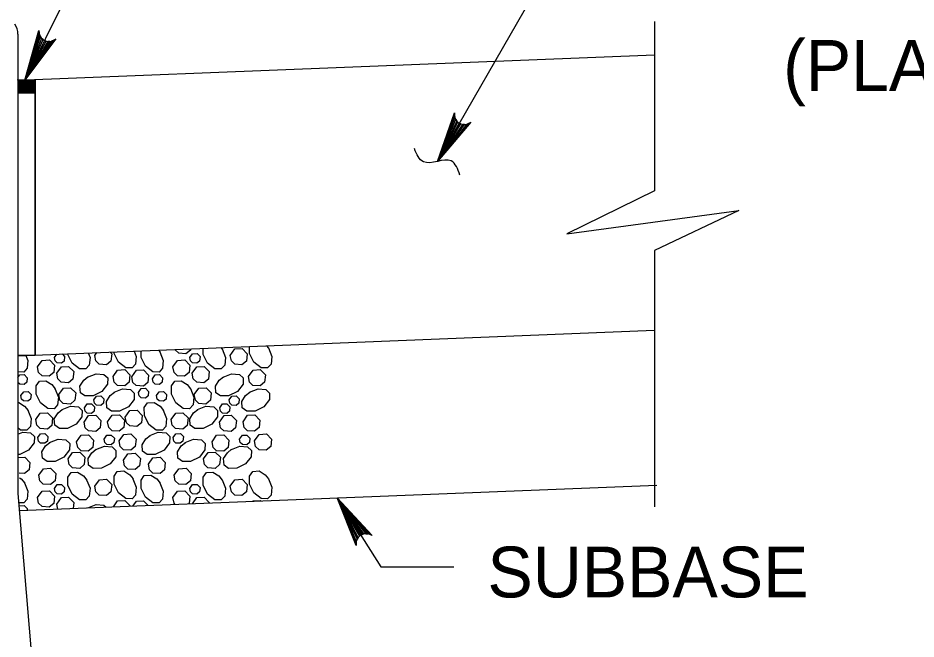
# Model space of a CAD drawing. Extents: x 2084213 to 2099800, y 976677 to 981262.
# Drawn here: x 2094550.7 to 2094724.7, y 976998 to 977118.3 of the extents above; entities that cross this region are included whole.
import ezdxf

# ---------------------------------------------------------------- set-up
doc = ezdxf.new("R2010")
doc.units = 0
doc.layers.add('1', color=7, linetype='Continuous')

msp = doc.modelspace()

# ---------------------------------------------------------------- linework, layer by layer
at = {"layer": '1'}
for p, q in [((2094594.99, 977193.27), (2094552.07, 977106.28)), ((2094631.96, 977090.51), (2094665.97, 977149.63)), ((2094674.05, 977117.63), (2094674.05, 977084.81)), ((2094550.71, 977115.18), (2094550.71, 977026.18)), ((2094550.71, 977106.22), (2094674.05, 977111.16)), ((2094550.71, 977106.2), (2094554.05, 977106.2)), ((2094550.71, 977106.05), (2094554.05, 977106.05)), ((2094550.71, 977105.9), (2094554.05, 977105.9)), ((2094550.71, 977105.75), (2094554.05, 977105.75)), ((2094554.05, 977106.36), (2094554.05, 977053)), ((2094550.71, 977105.6), (2094554.05, 977105.6)), ((2094550.71, 977105.45), (2094554.05, 977105.45)), ((2094550.71, 977105.3), (2094554.05, 977105.3)), ((2094550.71, 977105.15), (2094554.05, 977105.15)), ((2094550.71, 977105), (2094554.05, 977105)), ((2094550.71, 977104.85), (2094554.05, 977104.85)), ((2094550.71, 977104.7), (2094554.05, 977104.7)), ((2094550.71, 977104.55), (2094554.05, 977104.55)), ((2094550.71, 977104.4), (2094554.05, 977104.4)), ((2094550.71, 977104.25), (2094554.05, 977104.25)), ((2094550.71, 977104.1), (2094554.05, 977104.1)), ((2094550.71, 977103.95), (2094554.05, 977103.95)), ((2094550.71, 977103.8), (2094554.05, 977103.8)), ((2094674.05, 977073.27), (2094674.05, 977023.6)), ((2094550.71, 977052.86), (2094674.05, 977057.8)), ((2094550.99, 977022.85), (2094674.45, 977027.79)), ((2094550.71, 977026.18), (2094559.62, 976919.33)), ((2094612.54, 977025.31), (2094621, 977011.95)), ((2094621, 977011.95), (2094635.14, 977011.95))]:
    msp.add_line(p, q, dxfattribs=at)
for points in [[(2094552.07, 977106.28), (2094554.75, 977115.87), (2094554.82, 977115.41), (2094554.89, 977114.96), (2094555.1, 977114.64), (2094555.3, 977114.32), (2094555.57, 977114.12), (2094555.84, 977113.93), (2094556.16, 977113.83), (2094556.48, 977113.74), (2094556.86, 977113.77), (2094557.24, 977113.8), (2094557.64, 977114.02), (2094558.04, 977114.24), (2094552.07, 977106.28), (2094557.64, 977114.02), (2094557.24, 977113.8), (2094552.07, 977106.28), (2094556.86, 977113.77), (2094556.48, 977113.74), (2094552.07, 977106.28), (2094556.16, 977113.83), (2094555.84, 977113.93), (2094552.07, 977106.28), (2094555.57, 977114.12), (2094555.3, 977114.32), (2094552.07, 977106.28), (2094555.1, 977114.64), (2094554.89, 977114.96), (2094552.07, 977106.28), (2094554.82, 977115.41)], [(2094631.96, 977090.51), (2094635.25, 977099.91), (2094635.28, 977099.45), (2094635.32, 977098.99), (2094635.51, 977098.66), (2094635.7, 977098.33), (2094635.95, 977098.11), (2094636.21, 977097.9), (2094636.52, 977097.79), (2094636.84, 977097.67), (2094637.22, 977097.68), (2094637.6, 977097.68), (2094638.01, 977097.88), (2094638.43, 977098.08), (2094631.96, 977090.51), (2094638.01, 977097.88), (2094637.6, 977097.68), (2094631.96, 977090.51), (2094637.22, 977097.68), (2094636.84, 977097.67), (2094631.96, 977090.51), (2094636.52, 977097.79), (2094636.21, 977097.9), (2094631.96, 977090.51), (2094635.95, 977098.11), (2094635.7, 977098.33), (2094631.96, 977090.51), (2094635.51, 977098.66), (2094635.32, 977098.99), (2094631.96, 977090.51), (2094635.28, 977099.45)], [(2094674.05, 977084.81), (2094657.03, 977076.49), (2094690.33, 977081.01), (2094674.05, 977073.27)], [(2094568.56, 977053.58), (2094568.87, 977053.25), (2094568.73, 977051.82), (2094567.86, 977051.1), (2094566.47, 977051.2), (2094565.82, 977051.84), (2094565.6, 977052.93)], [(2094573.23, 977053.76), (2094573.64, 977052.74), (2094573.51, 977051.22), (2094572.82, 977050.5), (2094571.59, 977050.52), (2094570.2, 977051.62), (2094569.35, 977053.31), (2094569.35, 977053.61)], [(2094578.22, 977053.59), (2094578.87, 977051.94), (2094578.74, 977050.42), (2094578.05, 977049.7), (2094576.82, 977049.72), (2094575.43, 977050.82), (2094574.58, 977052.51), (2094574.56, 977053.82)], [(2094577.92, 977053.95), (2094578.26, 977053.52)], [(2094584.14, 977054.2), (2094584.12, 977053.96), (2094583.25, 977053.24), (2094581.86, 977053.34), (2094581.2, 977053.97), (2094581.18, 977054.08)], [(2094590.25, 977054.18), (2094590.91, 977052.53), (2094590.77, 977051.01), (2094590.09, 977050.29), (2094588.86, 977050.31), (2094587.46, 977051.4), (2094586.62, 977053.09), (2094586.59, 977054.3)], [(2094590.03, 977054.43), (2094590.29, 977054.11)], [(2094591.84, 977052.93), (2094592.72, 977054.18), (2094594.13, 977054.26), (2094595.11, 977053.25), (2094594.96, 977051.82), (2094594.09, 977051.1), (2094592.7, 977051.2), (2094592.05, 977051.84), (2094591.84, 977052.93)], [(2094599.22, 977054.39), (2094599.87, 977052.74), (2094599.74, 977051.22), (2094599.06, 977050.5), (2094597.83, 977050.52), (2094596.43, 977051.62), (2094595.58, 977053.31), (2094595.56, 977054.66)], [(2094598.89, 977054.79), (2094599.26, 977054.32)], [(2094552.25, 977052.92), (2094552.64, 977051.94), (2094552.51, 977050.42), (2094551.82, 977049.7), (2094550.71, 977049.72)], [(2094554.51, 977050.7), (2094555.39, 977051.96), (2094556.8, 977052.04), (2094557.78, 977051.02), (2094557.64, 977049.6), (2094556.77, 977048.88), (2094555.38, 977048.98), (2094554.72, 977049.61), (2094554.51, 977050.7)], [(2094559.25, 977053.2), (2094559.75, 977052.68), (2094559.67, 977051.83), (2094559.14, 977051.39), (2094558.31, 977051.46), (2094557.92, 977051.84), (2094557.79, 977052.49)], [(2094557.79, 977052.49), (2094558.26, 977053.16)], [(2094564.32, 977053.41), (2094564.67, 977052.53), (2094564.54, 977051.01), (2094563.86, 977050.29), (2094562.63, 977050.31), (2094561.23, 977051.4), (2094560.38, 977053.09), (2094560.38, 977053.25)], [(2094565.6, 977052.93), (2094565.99, 977053.47)], [(2094580.74, 977050.7), (2094581.62, 977051.96), (2094583.03, 977052.04), (2094584.01, 977051.02), (2094583.87, 977049.6), (2094583, 977048.88), (2094581.61, 977048.98), (2094580.95, 977049.61), (2094580.74, 977050.7)], [(2094584.02, 977052.49), (2094584.55, 977053.24), (2094585.4, 977053.29), (2094585.98, 977052.68), (2094585.9, 977051.83), (2094585.38, 977051.39), (2094584.54, 977051.46), (2094584.15, 977051.84), (2094584.02, 977052.49)], [(2094558.24, 977049.46), (2094559.12, 977050.71), (2094560.53, 977050.79), (2094561.51, 977049.78), (2094561.37, 977048.35), (2094560.5, 977047.63), (2094559.11, 977047.73), (2094558.45, 977048.37), (2094558.24, 977049.46)], [(2094569.13, 977048.84), (2094570.02, 977050.09), (2094571.43, 977050.17), (2094572.4, 977049.16), (2094572.26, 977047.73), (2094571.39, 977047.01), (2094570, 977047.11), (2094569.35, 977047.74), (2094569.14, 977048.83)], [(2094572.76, 977048.78), (2094573.65, 977050.04), (2094575.05, 977050.12), (2094576.03, 977049.1), (2094575.89, 977047.68), (2094575.02, 977046.96), (2094573.63, 977047.06), (2094572.98, 977047.69), (2094572.76, 977048.78)], [(2094584.47, 977049.46), (2094585.35, 977050.71), (2094586.76, 977050.79), (2094587.74, 977049.78), (2094587.6, 977048.35), (2094586.73, 977047.63), (2094585.34, 977047.73), (2094584.68, 977048.37), (2094584.47, 977049.46)], [(2094595.37, 977048.84), (2094596.25, 977050.09), (2094597.66, 977050.17), (2094598.64, 977049.16), (2094598.49, 977047.73), (2094597.62, 977047.01), (2094596.23, 977047.11), (2094595.58, 977047.74), (2094595.37, 977048.83)], [(2094550.71, 977048.63), (2094551.08, 977049.15), (2094551.92, 977049.2), (2094552.51, 977048.59), (2094552.42, 977047.73), (2094551.9, 977047.3), (2094551.07, 977047.36), (2094550.71, 977047.7)], [(2094564.21, 977048.72), (2094565.86, 977049.37), (2094567.38, 977049.24), (2094568.1, 977048.56), (2094568.08, 977047.33), (2094566.98, 977045.93), (2094565.29, 977045.09), (2094563.7, 977045.06), (2094562.8, 977045.69), (2094562.72, 977046.96), (2094563.45, 977048.1), (2094564.28, 977048.76)], [(2094576.78, 977048.39), (2094577.31, 977049.15), (2094578.15, 977049.2), (2094578.74, 977048.59), (2094578.66, 977047.73), (2094578.13, 977047.3), (2094577.3, 977047.36), (2094576.91, 977047.74), (2094576.78, 977048.39)], [(2094590.45, 977048.72), (2094592.1, 977049.37), (2094593.61, 977049.24), (2094594.33, 977048.56), (2094594.31, 977047.33), (2094593.22, 977045.93), (2094591.53, 977045.09), (2094589.93, 977045.06), (2094589.04, 977045.69), (2094588.95, 977046.96), (2094589.68, 977048.1), (2094590.51, 977048.76)], [(2094557.88, 977046.49), (2094558.54, 977044.84), (2094558.4, 977043.32), (2094557.72, 977042.6), (2094556.49, 977042.63), (2094555.09, 977043.72), (2094554.25, 977045.41), (2094554.22, 977047), (2094554.86, 977047.9), (2094556.12, 977047.98), (2094557.26, 977047.26), (2094557.92, 977046.42)], [(2094558.63, 977045.33), (2094559.51, 977046.58), (2094560.92, 977046.66), (2094561.9, 977045.65), (2094561.76, 977044.23), (2094560.89, 977043.5), (2094559.5, 977043.6), (2094558.84, 977044.24), (2094558.63, 977045.33)], [(2094574.05, 977045.75), (2094574.58, 977046.5), (2094575.42, 977046.55), (2094576.01, 977045.94), (2094575.92, 977045.08), (2094575.4, 977044.65), (2094574.57, 977044.71), (2094574.18, 977045.09), (2094574.05, 977045.75)], [(2094584.11, 977046.49), (2094584.77, 977044.84), (2094584.64, 977043.32), (2094583.95, 977042.6), (2094582.72, 977042.63), (2094581.32, 977043.72), (2094580.48, 977045.41), (2094580.45, 977047), (2094581.09, 977047.9), (2094582.36, 977047.98), (2094583.49, 977047.26), (2094584.16, 977046.42)], [(2094584.86, 977045.33), (2094585.74, 977046.58), (2094587.15, 977046.66), (2094588.13, 977045.65), (2094587.99, 977044.23), (2094587.12, 977043.5), (2094585.73, 977043.6), (2094585.08, 977044.24), (2094584.86, 977045.33)], [(2094551.29, 977045.13), (2094551.82, 977045.88), (2094552.67, 977045.93), (2094553.25, 977045.32), (2094553.17, 977044.46), (2094552.65, 977044.03), (2094551.81, 977044.09), (2094551.42, 977044.47), (2094551.29, 977045.13)], [(2094565.4, 977044.3), (2094565.93, 977045.05), (2094566.78, 977045.1), (2094567.36, 977044.49), (2094567.28, 977043.64), (2094566.76, 977043.2), (2094565.92, 977043.26), (2094565.53, 977043.64), (2094565.4, 977044.3)], [(2094569.33, 977045.77), (2094570.98, 977046.43), (2094572.5, 977046.3), (2094573.22, 977045.61), (2094573.2, 977044.38), (2094572.1, 977042.98), (2094570.41, 977042.14), (2094568.82, 977042.11), (2094567.92, 977042.75), (2094567.84, 977044.02), (2094568.57, 977045.15), (2094569.4, 977045.81)], [(2094577.52, 977045.13), (2094578.05, 977045.88), (2094578.9, 977045.93), (2094579.49, 977045.32), (2094579.4, 977044.46), (2094578.88, 977044.03), (2094578.04, 977044.09), (2094577.65, 977044.47), (2094577.52, 977045.13)], [(2094591.63, 977044.3), (2094592.16, 977045.05), (2094593.01, 977045.1), (2094593.59, 977044.49), (2094593.51, 977043.64), (2094592.99, 977043.2), (2094592.15, 977043.26), (2094591.76, 977043.64), (2094591.63, 977044.3)], [(2094595.57, 977045.77), (2094597.22, 977046.43), (2094598.73, 977046.3), (2094599.45, 977045.61), (2094599.43, 977044.38), (2094598.34, 977042.98), (2094596.65, 977042.14), (2094595.05, 977042.11), (2094594.16, 977042.75), (2094594.07, 977044.02), (2094594.8, 977045.15), (2094595.63, 977045.81)], [(2094550.71, 977043.81), (2094550.87, 977043.82), (2094552, 977043.09), (2094552.67, 977042.26)], [(2094559.25, 977042.41), (2094560.9, 977043.06), (2094562.41, 977042.93), (2094563.13, 977042.25), (2094563.11, 977041.02), (2094562.02, 977039.62), (2094560.33, 977038.78), (2094558.74, 977038.75), (2094557.84, 977039.38), (2094557.75, 977040.65), (2094558.48, 977041.79), (2094559.31, 977042.45)], [(2094563.58, 977042.77), (2094564.11, 977043.52), (2094564.96, 977043.57), (2094565.54, 977042.96), (2094565.46, 977042.11), (2094564.94, 977041.67), (2094564.1, 977041.73), (2094563.71, 977042.11), (2094563.58, 977042.77)], [(2094578.86, 977042.33), (2094579.51, 977040.68), (2094579.38, 977039.16), (2094578.69, 977038.44), (2094577.46, 977038.46), (2094576.07, 977039.56), (2094575.22, 977041.25), (2094575.19, 977042.84), (2094575.83, 977043.74), (2094577.1, 977043.82), (2094578.23, 977043.09), (2094578.9, 977042.26)], [(2094585.48, 977042.41), (2094587.13, 977043.06), (2094588.65, 977042.93), (2094589.37, 977042.25), (2094589.34, 977041.02), (2094588.25, 977039.62), (2094586.56, 977038.78), (2094584.97, 977038.75), (2094584.07, 977039.38), (2094583.99, 977040.65), (2094584.71, 977041.79), (2094585.55, 977042.45)], [(2094589.81, 977042.77), (2094590.34, 977043.52), (2094591.19, 977043.57), (2094591.77, 977042.96), (2094591.69, 977042.11), (2094591.17, 977041.67), (2094590.33, 977041.73), (2094589.94, 977042.11), (2094589.81, 977042.77)], [(2094552.62, 977042.33), (2094553.28, 977040.68), (2094553.15, 977039.16), (2094552.46, 977038.44), (2094551.23, 977038.46), (2094550.71, 977038.87)], [(2094554.16, 977040.48), (2094555.04, 977041.73), (2094556.45, 977041.81), (2094557.43, 977040.8), (2094557.29, 977039.37), (2094556.42, 977038.65), (2094555.03, 977038.75), (2094554.37, 977039.38), (2094554.16, 977040.48)], [(2094563.52, 977040.01), (2094564.4, 977041.26), (2094565.81, 977041.35), (2094566.79, 977040.33), (2094566.65, 977038.91), (2094565.78, 977038.18), (2094564.39, 977038.28), (2094563.74, 977038.92), (2094563.52, 977040.01)], [(2094568.07, 977040.06), (2094568.96, 977041.32), (2094570.37, 977041.4), (2094571.34, 977040.38), (2094571.2, 977038.96), (2094570.33, 977038.24), (2094568.94, 977038.34), (2094568.29, 977038.97), (2094568.08, 977040.06)], [(2094571.5, 977040.98), (2094572.38, 977042.24), (2094573.79, 977042.32), (2094574.77, 977041.3), (2094574.62, 977039.88), (2094573.75, 977039.16), (2094572.36, 977039.26), (2094571.71, 977039.89), (2094571.5, 977040.98)], [(2094580.39, 977040.48), (2094581.27, 977041.73), (2094582.68, 977041.81), (2094583.66, 977040.8), (2094583.52, 977039.37), (2094582.65, 977038.65), (2094581.26, 977038.75), (2094580.6, 977039.38), (2094580.39, 977040.48)], [(2094589.75, 977040.01), (2094590.64, 977041.26), (2094592.04, 977041.35), (2094593.02, 977040.33), (2094592.88, 977038.91), (2094592.01, 977038.18), (2094590.62, 977038.28), (2094589.97, 977038.92), (2094589.75, 977040.01)], [(2094594.31, 977040.06), (2094595.19, 977041.32), (2094596.6, 977041.4), (2094597.58, 977040.38), (2094597.43, 977038.96), (2094596.56, 977038.24), (2094595.17, 977038.34), (2094594.52, 977038.97), (2094594.31, 977040.06)], [(2094550.71, 977037.66), (2094551.66, 977038.03), (2094553.17, 977037.9), (2094553.9, 977037.22), (2094553.87, 977035.99), (2094552.78, 977034.59), (2094551.09, 977033.74), (2094550.71, 977033.74)], [(2094576.24, 977037.38), (2094577.89, 977038.03), (2094579.41, 977037.9), (2094580.13, 977037.22), (2094580.1, 977035.99), (2094579.01, 977034.59), (2094577.32, 977033.74), (2094575.73, 977033.71), (2094574.83, 977034.35), (2094574.75, 977035.62), (2094575.47, 977036.76), (2094576.31, 977037.42)], [(2094554.56, 977036.99), (2094555.09, 977037.74), (2094555.94, 977037.79), (2094556.52, 977037.18), (2094556.44, 977036.33), (2094555.92, 977035.89), (2094555.08, 977035.95), (2094554.69, 977036.33), (2094554.56, 977036.99)], [(2094556.85, 977036.02), (2094558.5, 977036.68), (2094560.01, 977036.55), (2094560.74, 977035.86), (2094560.71, 977034.63), (2094559.62, 977033.23), (2094557.93, 977032.39), (2094556.34, 977032.36), (2094555.44, 977033), (2094555.35, 977034.27), (2094556.08, 977035.4), (2094556.91, 977036.07)], [(2094562.08, 977036.18), (2094562.96, 977037.44), (2094564.37, 977037.52), (2094565.35, 977036.5), (2094565.2, 977035.08), (2094564.33, 977034.36), (2094562.94, 977034.46), (2094562.29, 977035.09), (2094562.08, 977036.18)], [(2094567.43, 977036.7), (2094567.96, 977037.45), (2094568.8, 977037.5), (2094569.39, 977036.89), (2094569.31, 977036.04), (2094568.78, 977035.6), (2094567.95, 977035.66), (2094567.56, 977036.04), (2094567.43, 977036.7)], [(2094570.32, 977036.37), (2094571.2, 977037.63), (2094572.61, 977037.71), (2094573.59, 977036.69), (2094573.45, 977035.27), (2094572.58, 977034.55), (2094571.19, 977034.65), (2094570.53, 977035.28), (2094570.32, 977036.37)], [(2094580.79, 977036.99), (2094581.32, 977037.74), (2094582.17, 977037.79), (2094582.76, 977037.18), (2094582.67, 977036.33), (2094582.15, 977035.89), (2094581.31, 977035.95), (2094580.92, 977036.33), (2094580.79, 977036.99)], [(2094583.08, 977036.02), (2094584.73, 977036.68), (2094586.25, 977036.55), (2094586.97, 977035.86), (2094586.94, 977034.63), (2094585.85, 977033.23), (2094584.16, 977032.39), (2094582.57, 977032.36), (2094581.67, 977033), (2094581.59, 977034.27), (2094582.31, 977035.4), (2094583.15, 977036.07)], [(2094588.31, 977036.18), (2094589.19, 977037.44), (2094590.6, 977037.52), (2094591.58, 977036.5), (2094591.44, 977035.08), (2094590.57, 977034.36), (2094589.17, 977034.46), (2094588.52, 977035.09), (2094588.31, 977036.18)], [(2094593.66, 977036.7), (2094594.19, 977037.45), (2094595.03, 977037.5), (2094595.62, 977036.89), (2094595.54, 977036.04), (2094595.02, 977035.6), (2094594.18, 977035.66), (2094593.79, 977036.04), (2094593.66, 977036.7)], [(2094596.55, 977036.37), (2094597.43, 977037.63), (2094598.84, 977037.71), (2094599.82, 977036.69), (2094599.68, 977035.27), (2094598.81, 977034.55), (2094597.42, 977034.65), (2094596.76, 977035.28), (2094596.55, 977036.37)], [(2094565.81, 977034.69), (2094567.46, 977035.34), (2094568.98, 977035.21), (2094569.7, 977034.53), (2094569.68, 977033.3), (2094568.58, 977031.9), (2094566.89, 977031.05), (2094565.3, 977031.03), (2094564.41, 977031.66), (2094564.32, 977032.93), (2094565.05, 977034.07), (2094565.88, 977034.73)], [(2094592.05, 977034.69), (2094593.7, 977035.34), (2094595.21, 977035.21), (2094595.93, 977034.53), (2094595.91, 977033.3), (2094594.82, 977031.9), (2094593.13, 977031.05), (2094591.53, 977031.03), (2094590.64, 977031.66), (2094590.55, 977032.93), (2094591.28, 977034.07), (2094592.11, 977034.73)], [(2094550.71, 977033.11), (2094552.03, 977033.18), (2094553.01, 977032.17), (2094552.87, 977030.75), (2094552, 977030.02), (2094550.95, 977030.1)], [(2094560.41, 977032.86), (2094561.3, 977034.12), (2094562.71, 977034.2), (2094563.69, 977033.18), (2094563.54, 977031.76), (2094562.67, 977031.04), (2094561.28, 977031.14), (2094560.63, 977031.77), (2094560.42, 977032.86)], [(2094571.15, 977032.62), (2094572.03, 977033.87), (2094573.44, 977033.95), (2094574.42, 977032.94), (2094574.28, 977031.51), (2094573.41, 977030.79), (2094572.02, 977030.89), (2094571.36, 977031.53), (2094571.15, 977032.62)], [(2094575.97, 977031.85), (2094576.86, 977033.1), (2094578.26, 977033.18), (2094579.24, 977032.17), (2094579.1, 977030.75), (2094578.23, 977030.02), (2094576.84, 977030.12), (2094576.19, 977030.76), (2094575.97, 977031.85)], [(2094586.65, 977032.86), (2094587.53, 977034.12), (2094588.94, 977034.2), (2094589.92, 977033.18), (2094589.78, 977031.76), (2094588.91, 977031.04), (2094587.51, 977031.14), (2094586.86, 977031.77), (2094586.65, 977032.86)], [(2094554.76, 977029.71), (2094555.64, 977030.97), (2094557.05, 977031.05), (2094558.03, 977030.03), (2094557.89, 977028.61), (2094557.02, 977027.89), (2094555.62, 977027.99), (2094554.97, 977028.62), (2094554.76, 977029.71)], [(2094580.99, 977029.71), (2094581.87, 977030.97), (2094583.28, 977031.05), (2094584.26, 977030.03), (2094584.12, 977028.61), (2094583.25, 977027.89), (2094581.86, 977027.99), (2094581.2, 977028.62), (2094580.99, 977029.71)], [(2094551.02, 977029.23), (2094551.36, 977029.01), (2094552.03, 977028.17)], [(2094564.02, 977028.83), (2094564.67, 977027.18), (2094564.54, 977025.66), (2094563.86, 977024.94), (2094562.63, 977024.96), (2094561.23, 977026.06), (2094560.38, 977027.75), (2094560.36, 977029.34), (2094560.99, 977030.24), (2094562.26, 977030.32), (2094563.4, 977029.59), (2094564.06, 977028.76)], [(2094572.99, 977029.04), (2094573.64, 977027.39), (2094573.51, 977025.87), (2094572.82, 977025.15), (2094571.59, 977025.18), (2094570.2, 977026.27), (2094569.35, 977027.96), (2094569.32, 977029.55), (2094569.96, 977030.45), (2094571.23, 977030.54), (2094572.36, 977029.81), (2094573.03, 977028.98)], [(2094578.22, 977028.24), (2094578.87, 977026.59), (2094578.74, 977025.07), (2094578.05, 977024.35), (2094576.82, 977024.38), (2094575.43, 977025.47), (2094574.58, 977027.16), (2094574.55, 977028.75), (2094575.19, 977029.65), (2094576.46, 977029.74), (2094577.59, 977029.01), (2094578.26, 977028.17)], [(2094590.25, 977028.83), (2094590.91, 977027.18), (2094590.77, 977025.66), (2094590.09, 977024.94), (2094588.86, 977024.96), (2094587.46, 977026.06), (2094586.62, 977027.75), (2094586.59, 977029.34), (2094587.22, 977030.24), (2094588.49, 977030.32), (2094589.63, 977029.59), (2094590.29, 977028.76)], [(2094599.22, 977029.04), (2094599.87, 977027.39), (2094599.74, 977025.87), (2094599.06, 977025.15), (2094597.83, 977025.18), (2094596.43, 977026.27), (2094595.58, 977027.96), (2094595.55, 977029.55), (2094596.19, 977030.45), (2094597.46, 977030.54), (2094598.59, 977029.81), (2094599.26, 977028.98)], [(2094551.98, 977028.24), (2094552.64, 977026.59), (2094552.51, 977025.07), (2094551.82, 977024.35), (2094550.87, 977024.37)], [(2094557.79, 977027.14), (2094558.32, 977027.9), (2094559.16, 977027.94), (2094559.75, 977027.33), (2094559.67, 977026.48), (2094559.14, 977026.05), (2094558.31, 977026.11), (2094557.92, 977026.49), (2094557.79, 977027.14)], [(2094565.6, 977027.58), (2094566.49, 977028.83), (2094567.89, 977028.92), (2094568.87, 977027.9), (2094568.73, 977026.48), (2094567.86, 977025.75), (2094566.47, 977025.85), (2094565.82, 977026.49), (2094565.6, 977027.58)], [(2094584.02, 977027.14), (2094584.55, 977027.9), (2094585.4, 977027.94), (2094585.98, 977027.33), (2094585.9, 977026.48), (2094585.38, 977026.05), (2094584.54, 977026.11), (2094584.15, 977026.49), (2094584.02, 977027.14)], [(2094591.84, 977027.58), (2094592.72, 977028.83), (2094594.13, 977028.92), (2094595.11, 977027.9), (2094594.96, 977026.48), (2094594.09, 977025.75), (2094592.7, 977025.85), (2094592.05, 977026.49), (2094591.84, 977027.58)], [(2094554.51, 977025.36), (2094555.39, 977026.61), (2094556.8, 977026.69), (2094557.78, 977025.68), (2094557.64, 977024.25), (2094556.77, 977023.53), (2094555.38, 977023.63), (2094554.72, 977024.27), (2094554.51, 977025.36)], [(2094580.74, 977025.36), (2094581.62, 977026.61), (2094583.03, 977026.69), (2094584.01, 977025.68), (2094583.87, 977024.25), (2094583.76, 977024.16)], [(2094558.24, 977024.11), (2094559.12, 977025.37), (2094560.53, 977025.45), (2094561.51, 977024.43), (2094561.39, 977023.26)], [(2094558.43, 977023.15), (2094558.24, 977024.11)], [(2094564.23, 977023.38), (2094565.86, 977024.03), (2094567.38, 977023.9), (2094567.78, 977023.52)], [(2094569.2, 977023.58), (2094570.02, 977024.74), (2094571.43, 977024.82), (2094572.4, 977023.81), (2094572.39, 977023.71)], [(2094572.97, 977023.73), (2094573.65, 977024.69), (2094575.05, 977024.77), (2094575.95, 977023.85)], [(2094581.17, 977024.06), (2094580.95, 977024.27), (2094580.74, 977025.36)], [(2094584.53, 977024.19), (2094585.35, 977025.37), (2094586.76, 977025.45), (2094587.74, 977024.43), (2094587.73, 977024.32)], [(2094596.19, 977024.66), (2094596.25, 977024.74), (2094597.66, 977024.82), (2094597.76, 977024.72)], [(2094612.54, 977025.31), (2094619.32, 977018.02), (2094618.9, 977018.2), (2094618.48, 977018.38), (2094618.1, 977018.37), (2094617.72, 977018.36), (2094617.41, 977018.23), (2094617.1, 977018.1), (2094616.85, 977017.88), (2094616.61, 977017.66), (2094616.43, 977017.32), (2094616.26, 977016.98), (2094616.24, 977016.52), (2094616.22, 977016.06), (2094612.54, 977025.31), (2094616.24, 977016.52), (2094616.26, 977016.98), (2094612.54, 977025.31), (2094616.43, 977017.32), (2094616.61, 977017.66), (2094612.54, 977025.31), (2094616.85, 977017.88), (2094617.1, 977018.1), (2094612.54, 977025.31), (2094617.41, 977018.23), (2094617.72, 977018.36), (2094612.54, 977025.31), (2094618.1, 977018.37), (2094618.48, 977018.38), (2094612.54, 977025.31), (2094618.9, 977018.2)], [(2094550.91, 977023.79), (2094551.92, 977023.85), (2094552.51, 977023.24), (2094552.48, 977022.91)], [(2094564.23, 977023.38), (2094564.28, 977023.42)]]:
    msp.add_lwpolyline(points, dxfattribs=at)
msp.add_lwpolyline([(2094554.05, 977106.22), (2094550.71, 977106.22), (2094550.71, 977106.36), (2094550.71, 977053), (2094554.05, 977053)], close=True, dxfattribs=at)
msp.add_arc((2094547.38, 977115.18), 3.33, 0, 34.8593, dxfattribs=at)
msp.add_arc((2094547.38, 977115.18), 3.33, 0, 34.8593, dxfattribs=at)
msp.add_spline([(2094636.34, 977087.86), (2094634.64, 977090.59), (2094629.25, 977090.42), (2094627.5, 977092.99)], degree=3, dxfattribs=at)

# ---------------------------------------------------------------- texts
for s, height, p in [('(PLACED CURB TO CURB)', 9.8425, (2094698.95, 977104.17)), ('SUBBASE', 9.843, (2094641.66, 977006.03))]:
    msp.add_text(s, height=height, dxfattribs=at).set_placement(p)

doc.saveas('drawing.dxf')
